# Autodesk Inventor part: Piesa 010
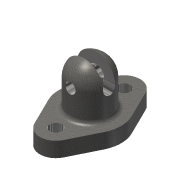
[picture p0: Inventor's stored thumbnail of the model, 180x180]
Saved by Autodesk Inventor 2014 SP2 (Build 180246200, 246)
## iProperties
Created: 2009-01
Part Number: Piesa 010
Document SubType Name: Modeling
Designer: Costel
Density: 7.85 g/cm^3
Material: Steel
Appearance: Steel - Polished
Mass: 696.896 g
Surface Area: 207.658 cm^2
Volume: 88.7766 cm^3
Author: Costel
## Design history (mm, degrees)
sketch "Sketch1"
  geometry: L1 (0, -60)-(0, 80) reference; L2 (-37.2, 0)-(49.6, 0) reference; L3 (-27.82, 13.676)-(-14.359, 41.059); L4 (14.359, 41.059)-(27.82, 13.676); L5 (-27.82, -13.676)-(-14.359, -41.059); L6 (14.359, -41.059)-(27.82, -13.676); C1 r 6 at (0, 34); C2 r 6 at (0, -34); A1 r 16 centre (0, 34) between (14.359, 41.059) and (-14.359, 41.059); A2 r 16 centre (0, -34) between (-14.359, -41.059) and (14.359, -41.059); A3 r 31 centre (0, 0) between (27.82, -13.676) and (27.82, 13.676); A4 r 31 centre (0, 0) between (-27.82, 13.676) and (-27.82, -13.676)
  constraints: 8 end point, 8 point on circle, 8 tangent, 6 centre point, 3 point on line, 2 symmetric about line, 1 coincident, 1 concentric, 2 other
  dimensions: "d0" = 16 radius of A1; "d1" = 31 radius of A3; "d2" = 68 distance of A2.centre A1.centre; "d3" = 12 diameter of C1
extrude "Extrusion1" new body sketch "Sketch1" distance "d4" = 15; taper "d5" = 0 deg
hole "Hole1" diameter "d8" = 20; stored, may be unused: countersink angle "d12" = 90 deg, drill point angle "d14" = 118 deg; dims "d6" = 10, "d7" = 10, "d9" = 6, "d10" = 4, "d11" = 2, "d13" = 8
sketch "Sketch2"
  geometry: L1 (-10, 42)-(-10, 15); L2 (0, -3.546)-(0, 46.096) reference; L3 (-14.359, 15)-(14.359, 15) reference; L4 (-20, 15)-(-20, 42); L5 (-10, 15)-(-20, 15); L6 (0, 62)-(0, 52); L7 (10, 0)-(-10, 0) reference; A1 r 10 centre (0, 42) between (0, 52) and (-10, 42); A2 r 20 centre (0, 42) between (0, 62) and (-20, 42)
  constraints: 8 end point, 4 point on circle, 2 centre point, 2 perpendicular, 2 point on line, 1 collinear, 1 tangent, 1 vertical, 1 other
  dimensions: "d15" = 42 distance from line of L7 A1.centre; "d16" = 20 diameter of L1 L2; "d17" = 40 diameter of L4 L2
revolve "Revolution1" sketch "Sketch2" stored, may be unused: angle "d18" = 90 deg
sketch "Sketch3"
  geometry: L1 (-6, 42)-(-6, 75.248); L2 (-6, 75.248)-(6, 75.248); L3 (6, 75.248)-(6, 42); A1 r 10 centre (0, 42) between (10, 42) and (-10, 42) reference; A2 r 6 centre (0, 42) between (-6, 42) and (6, 42)
  constraints: 6 end point, 2 point on circle, 2 tangent, 1 centre point, 1 coincident, 1 parallel, 1 perpendicular, 1 vertical
  dimensions: "d19" = 6 radius of A2
extrude "Extrusion2" cut sketch "Sketch3" stored distance "d20" = 10; taper "d21" = 0 deg
sketch "Sketch4"
  geometry: L1 (0, -6.108)-(0, 79.402) reference; L2 (10, 0)-(-10, 0) reference; C1 r 5 at (0, 42)
  constraints: 1 centre point, 1 point on line
  dimensions: "d22" = 42 distance from line of L2 C1.centre (= d15); "d25" = 10 diameter of C1
extrude "Extrusion3" cut sketch "Sketch4" stored distance "d23" = 10; taper "d24" = 0 deg
fillet "Fillet1" dims "d26" = 4
body "Solid1"
